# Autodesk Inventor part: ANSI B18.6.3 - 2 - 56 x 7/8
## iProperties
Comments: To add or edit properties for Autodesk Inventor files, use iProperties.
Created: 2004-04
Part Number: ANSI B18.6.3 - 2 - 56 x 7/8
Vendor: Autodesk Inc.
Document SubType Name: Modeling
Designer: jpittman
Material: Default
Description: Slotted Pan Head Machine Screw
Standard: ANSI B18.6.3
Alert: To add or edit properties for Autodesk Inventor files, use iProperties.
Control State: 0
Master: False
Checked Out: False
Shininess: 64.0
Length Units: 11272
Angle Units: 11279
Time Units: 11290
Mass Units: 11286
Length Display Precision: 3
Angle Display Precision: 2
Compacted: True
EGR: 3
Classification: un/spsc 31161504
Density: 0.0
Volumn: 0.0
Area: 0.0
PropertySet Name: Model Information
Author: jpittman
Revision Number: 12
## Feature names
1. Body [Revolution]
2. Fillet1
3. Slot [Extrusion]
4. Chamfer1
